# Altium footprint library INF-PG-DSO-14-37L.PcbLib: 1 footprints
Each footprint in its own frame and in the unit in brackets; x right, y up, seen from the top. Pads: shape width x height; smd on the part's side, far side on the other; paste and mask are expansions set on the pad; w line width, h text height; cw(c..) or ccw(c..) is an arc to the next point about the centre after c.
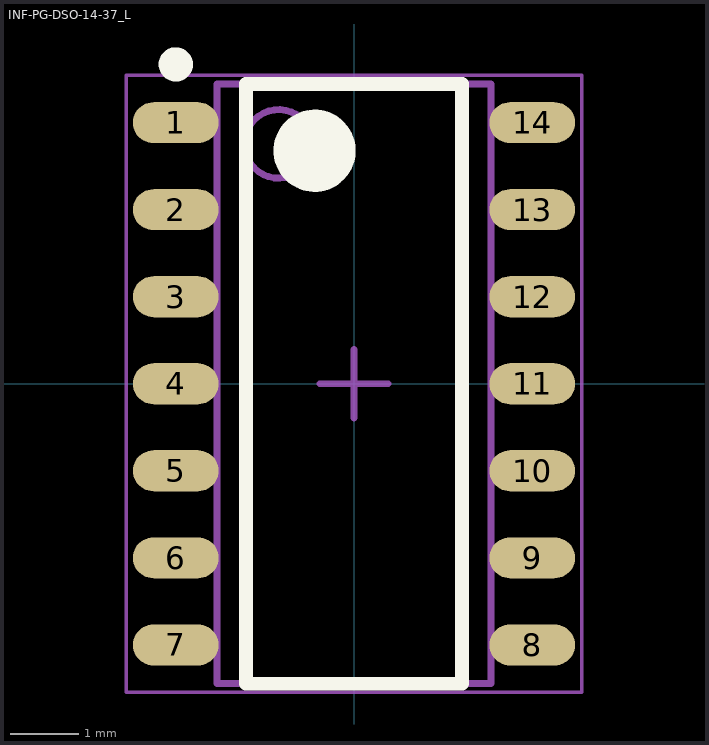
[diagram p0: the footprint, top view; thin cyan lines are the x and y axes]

## INF-PG-DSO-14-37_L [mm] "SOP, 14-Leads, Body 8.65x3.9mm, Pitch 1.27mm, IPC High Density"
height 1.75
pads (14):
  oval 1.25x0.6 smd: 1(-2.6,3.81) 2(-2.6,2.54) 3(-2.6,1.27) 4(-2.6,0) 5(-2.6,-1.27) 6(-2.6,-2.54) 7(-2.6,-3.81) 8(2.6,-3.81) 9(2.6,-2.54) 10(2.6,-1.27) 11(2.6,0) 12(2.6,1.27) 13(2.6,2.54) 14(2.6,3.81)
Top Overlay:
  circle w0.6: c-0.575,3.4 r0.3
  circle w0.25: c-2.6,4.66 r0.125
  lines w0.2: -1.575,-4.375 1.575,-4.375 1.575,4.375 -1.575,4.375 -1.575,-4.375
Mechanical 13:
  circle w0.1: c-1.1,3.5 r0.5
  lines w0.1: -2,-4.375 2,-4.375 2,4.375 -2,4.375 -2,-4.375
Mechanical 15:
  lines w0.05: -3.325,-4.5 3.325,-4.5 3.325,4.5 -3.325,4.5 -3.325,-4.5
  lines w0.1: -0.5,0 0.5,0 ; 0,-0.5 0,0.5
3D body: height 1.75, standoff 0.11, extent -2,-4.375 2,4.375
